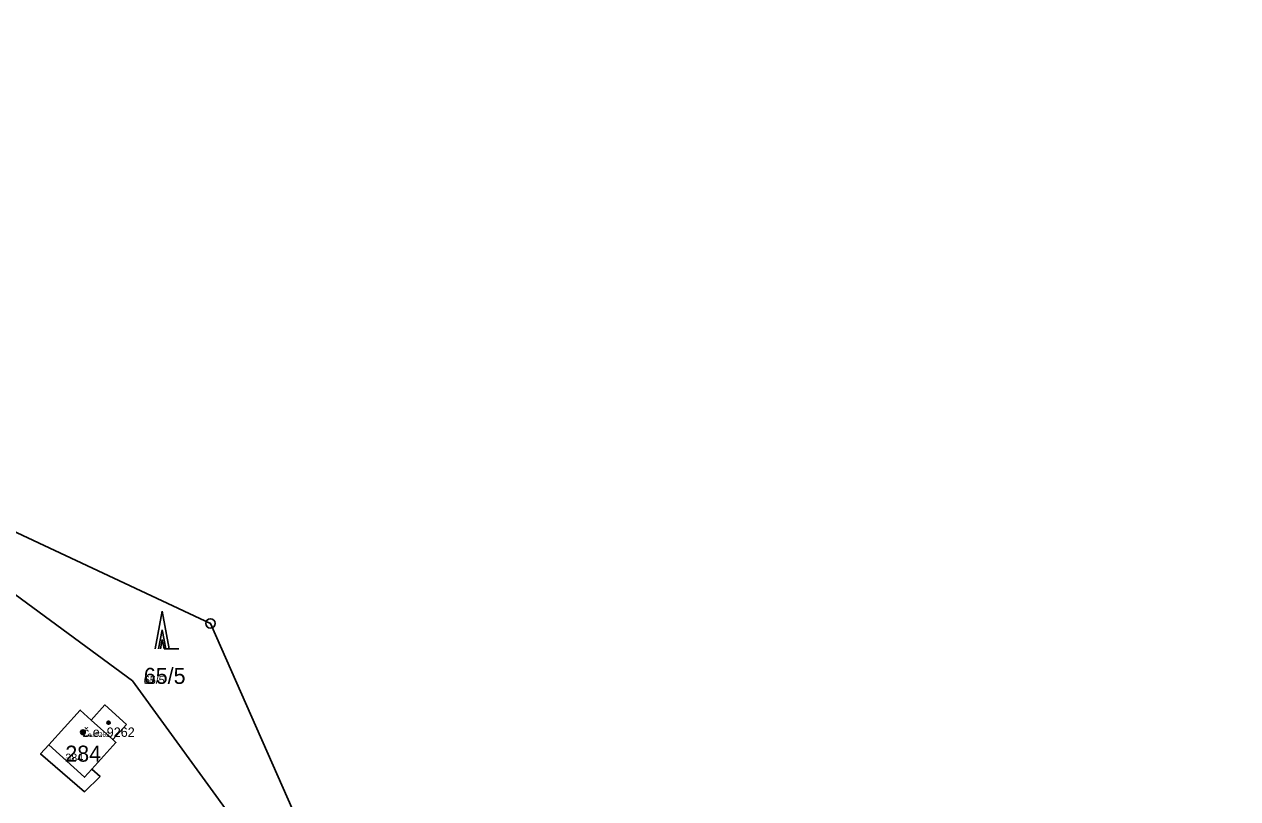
# Model space of a CAD drawing. Extents: x -759873 to -758487, y -975024 to -973516.
# Drawn here: x -758816.8 to -758688, y -974382.1 to -974299.8 of the extents above; entities that cross this region are included whole.
import ezdxf

# ---------------------------------------------------------------- set-up
doc = ezdxf.new("R2010")
doc.units = 0
for name, color, linetype in [('KAT_02_hranice parcel', 7, 'Continuous'), ('KAT_03_1000_st čísla parcelní', 7, 'Continuous'), ('KAT_03_1000_čísla parcelní', 7, 'Continuous'), ('KAT_03_1000_čísla popisná', 7, 'Continuous'), ('KAT_03_250_st čísla parcelní', 7, 'Continuous'), ('KAT_03_250_čísla parcelní', 7, 'Continuous'), ('KAT_03_250_čísla popisná', 7, 'Continuous'), ('KAT_03_500_st čísla parcelní', 7, 'Continuous'), ('KAT_03_500_čísla parcelní', 7, 'Continuous'), ('KAT_03_500_čísla popisná', 7, 'Continuous'), ('KAT_04_vnitřní kresba', 7, 'Continuous'), ('KAT_05_1000_značky kultur', 7, 'Continuous'), ('KAT_05_250_značky kultur', 7, 'Continuous'), ('KAT_05_500_značky kultur', 7, 'Continuous'), ('KAT_07_1000_značky budov', 7, 'Continuous'), ('KAT_07_250_značky budov', 7, 'Continuous'), ('KAT_07_500_značky budov', 7, 'Continuous'), ('KAT_11_značky bodu BP', 7, 'Continuous'), ('KAT_14_plocha_budovy', 7, 'Continuous'), ('KAT_14_plocha_pozemek', 7, 'Continuous')]:
    doc.layers.add(name, color=color, linetype=linetype)

msp = doc.modelspace()

# ---------------------------------------------------------------- linework, layer by layer
at = {"layer": 'KAT_02_hranice parcel'}
for points in [[(-758632.75, -974453.28), (-758635.81, -974453.89), (-758660.34, -974450.22), (-758670.25, -974448.59), (-758679.84, -974446.31), (-758718.48, -974444.93), (-758753.38, -974423.47), (-758781.23, -974399.3), (-758797.06, -974363.45), (-758834.16, -974346.1), (-758865.99, -974333.25), (-758907.24, -974318.32), (-758952.22, -974315.62)], [(-758822.78, -974356.75), (-758805.35, -974369.54), (-758794.34, -974384.71)], [(-758805.99, -974374.17), (-758807.44, -974375.78), (-758807.1, -974376.09), (-758809.66, -974378.92), (-758808.78, -974379.72), (-758810.43, -974381.32), (-758815.09, -974377.31), (-758814.22, -974376.35), (-758810.88, -974372.66), (-758809.73, -974373.71), (-758808.28, -974372.1), (-758805.99, -974374.17)]]:
    msp.add_lwpolyline(points, dxfattribs=at)
at = {"layer": 'KAT_03_1000_čísla popisná'}
msp.add_circle((-758810.6, -974375), 0.25, dxfattribs=at)
at = {"layer": 'KAT_03_250_čísla popisná'}
msp.add_circle((-758810.6, -974375), 0.0625, dxfattribs=at)
at = {"layer": 'KAT_03_500_čísla popisná'}
msp.add_circle((-758810.6, -974375), 0.125, dxfattribs=at)
at = {"layer": 'KAT_04_vnitřní kresba'}
for p, q in [((-758809.73, -974373.71), (-758807.44, -974375.78)), ((-758814.22, -974376.35), (-758810.44, -974379.78)), ((-758810.44, -974379.78), (-758809.66, -974378.92))]:
    msp.add_line(p, q, dxfattribs=at)
at = {"layer": 'KAT_05_1000_značky kultur'}
for p, q in [((-758802.18, -974362.15), (-758802.93, -974366.15)), ((-758801.43, -974366.15), (-758802.18, -974362.15)), ((-758801.43, -974366.15), (-758800.43, -974366.15))]:
    msp.add_line(p, q, dxfattribs=at)
at = {"layer": 'KAT_05_250_značky kultur'}
for p, q in [((-758802.18, -974365.15), (-758802.37, -974366.15)), ((-758801.99, -974366.15), (-758802.18, -974365.15)), ((-758801.99, -974366.15), (-758801.74, -974366.15))]:
    msp.add_line(p, q, dxfattribs=at)
at = {"layer": 'KAT_05_500_značky kultur'}
for p, q in [((-758802.18, -974364.15), (-758802.56, -974366.15)), ((-758801.81, -974366.15), (-758802.18, -974364.15)), ((-758801.81, -974366.15), (-758801.31, -974366.15))]:
    msp.add_line(p, q, dxfattribs=at)
at = {"layer": 'KAT_07_1000_značky budov'}
for centre in [(-758807.88, -974373.99), (-758810.61, -974375)]:
    msp.add_circle(centre, 0.175, dxfattribs=at)
at = {"layer": 'KAT_07_250_značky budov'}
for centre in [(-758807.87, -974373.99), (-758810.6, -974375)]:
    msp.add_circle(centre, 0.0437, dxfattribs=at)
at = {"layer": 'KAT_07_500_značky budov'}
for centre in [(-758807.87, -974373.99), (-758810.6, -974375)]:
    msp.add_circle(centre, 0.0875, dxfattribs=at)
at = {"layer": 'KAT_11_značky bodu BP'}
for radius in [0.5, 0.0303]:
    msp.add_circle((-758797.06, -974363.45), radius, dxfattribs=at)
at = {"layer": 'KAT_14_plocha_budovy'}
msp.add_lwpolyline([(-758809.66, -974378.92), (-758807.1, -974376.09), (-758807.44, -974375.78), (-758809.73, -974373.71), (-758810.88, -974372.66), (-758814.22, -974376.35), (-758810.44, -974379.78)], close=True, dxfattribs=at)
at = {"layer": 'KAT_14_plocha_pozemek'}
for points in [[(-758834.16, -974346.1), (-758797.06, -974363.45), (-758781.23, -974399.3), (-758753.38, -974423.47), (-758718.48, -974444.93), (-758679.84, -974446.31), (-758670.25, -974448.59), (-758660.34, -974450.22), (-758635.81, -974453.89), (-758632.75, -974453.28), (-758613.64, -974443.17), (-758592.01, -974425.87), (-758584.15, -974408.39), (-758577.48, -974373.63), (-758560.12, -974371.49), (-758566.72, -974342.84), (-758577.45, -974305.32), (-758579.96, -974284.59)], [(-758822.78, -974356.75), (-758805.35, -974369.54), (-758794.34, -974384.71), (-758781.96, -974405.06), (-758777.78, -974408.08), (-758761.72, -974419.22), (-758750.8, -974427.84), (-758717.38, -974449.33), (-758718.12, -974451.24), (-758682.5, -974452.45), (-758640.39, -974457.49), (-758627.86, -974462.19), (-758632.75, -974453.28), (-758635.81, -974453.89), (-758660.34, -974450.22), (-758670.25, -974448.59), (-758679.84, -974446.31), (-758718.48, -974444.93), (-758753.38, -974423.47), (-758781.23, -974399.3), (-758797.06, -974363.45), (-758834.16, -974346.1)]]:
    msp.add_lwpolyline(points, dxfattribs=at)
for points in [[(-758822.78, -974356.75), (-758836.14, -974378.49), (-758829.57, -974379.17), (-758829.43, -974382.81), (-758810.18, -974401.15), (-758794.34, -974384.71), (-758805.35, -974369.54)], [(-758805.99, -974374.17), (-758807.44, -974375.78), (-758807.1, -974376.09), (-758809.66, -974378.92), (-758808.78, -974379.72), (-758810.43, -974381.32), (-758815.09, -974377.31), (-758814.22, -974376.35), (-758810.88, -974372.66), (-758809.73, -974373.71), (-758808.28, -974372.1)], [(-758805.99, -974374.17), (-758808.28, -974372.1), (-758809.73, -974373.71), (-758810.88, -974372.66), (-758814.22, -974376.35), (-758815.09, -974377.31), (-758810.43, -974381.32), (-758808.78, -974379.72), (-758809.66, -974378.92), (-758807.1, -974376.09), (-758807.44, -974375.78)]]:
    msp.add_lwpolyline(points, close=True, dxfattribs=at)

# ---------------------------------------------------------------- texts
at = {"layer": 'KAT_03_1000_st čísla parcelní'}
msp.add_text('284', height=1.7, dxfattribs=at).set_placement((-758812.47, -974378.13))
at = {"layer": 'KAT_03_1000_čísla parcelní'}
msp.add_text('65/5', height=1.7, dxfattribs=at).set_placement((-758804.13, -974369.87))
at = {"layer": 'KAT_03_1000_čísla popisná'}
msp.add_text('č.e. 9262', height=1, dxfattribs=at).set_placement((-758810.6, -974375.5))
at = {"layer": 'KAT_03_250_st čísla parcelní'}
msp.add_text('284', height=0.425, dxfattribs=at).set_placement((-758812.47, -974378.13))
at = {"layer": 'KAT_03_250_čísla parcelní'}
msp.add_text('65/5', height=0.425, dxfattribs=at).set_placement((-758804.13, -974369.87))
at = {"layer": 'KAT_03_250_čísla popisná'}
msp.add_text('č.e. 9262', height=0.25, dxfattribs=at).set_placement((-758810.6, -974375.5))
at = {"layer": 'KAT_03_500_st čísla parcelní'}
msp.add_text('284', height=0.85, dxfattribs=at).set_placement((-758812.47, -974378.13))
at = {"layer": 'KAT_03_500_čísla parcelní'}
msp.add_text('65/5', height=0.85, dxfattribs=at).set_placement((-758804.13, -974369.87))
at = {"layer": 'KAT_03_500_čísla popisná'}
msp.add_text('č.e. 9262', height=0.5, dxfattribs=at).set_placement((-758810.6, -974375.5))

doc.saveas('drawing.dxf')
